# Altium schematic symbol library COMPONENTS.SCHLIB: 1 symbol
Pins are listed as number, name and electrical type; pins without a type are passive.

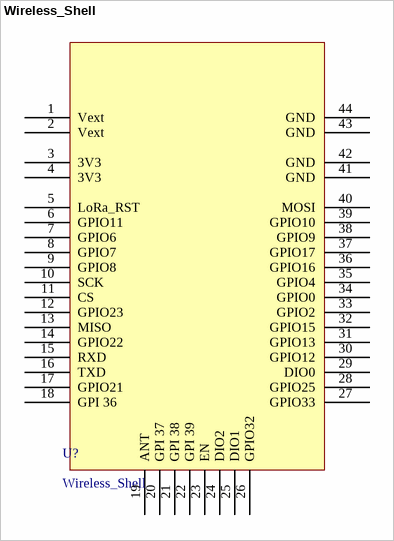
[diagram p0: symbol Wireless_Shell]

## Wireless_Shell
designator U?
footprint Esp_PICO
pins: 1 Vext, 2 Vext, 3 3V3, 4 3V3, 5 LoRa_RST, 6 GPIO11, 7 GPIO6, 8 GPIO7, 9 GPIO8, 10 SCK, 11 CS, 12 GPIO23, 13 MISO, 14 GPIO22, 15 RXD, 16 TXD, 17 GPIO21, 18 GPI 36, 19 ANT, 20 GPI 37, 21 GPI 38, 22 GPI 39, 23 EN, 24 DIO2, 25 DIO1, 26 GPIO32, 27 GPIO33, 28 GPIO25, 29 DIO0, 30 GPIO12, 31 GPIO13, 32 GPIO15, 33 GPIO2, 34 GPIO0, 35 GPIO4, 36 GPIO16, 37 GPIO17, 38 GPIO9, 39 GPIO10, 40 MOSI, 41 GND, 42 GND, 43 GND, 44 GND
